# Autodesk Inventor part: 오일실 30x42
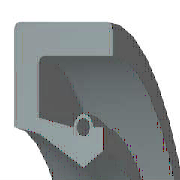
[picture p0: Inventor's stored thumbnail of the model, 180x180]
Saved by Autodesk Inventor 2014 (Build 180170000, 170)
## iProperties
IsCustomPart: 0
Company: 한국ATC센터
Created: 2009-02
Part Number: 오일실 30x42
Material: 고무
Description: 오일-실
Document SubType Name: Modeling
Standard: KS B 2804
Designer: KYOUNG IL JANG
Standards Organization: KS
Language: ko-KR
Size Designation: S - 30 42 8
Categories: <MemberInstance><Categories><Category DisplayName="샤프트 부품" InternalName="7f7aeb1f-a693-4053-b835-cee3144e0d98" Mnemonic="SHFT"><Category DisplayName="실링" Intern
Density: 0.93 g/cm^3
Appearance: 고무 - 검은색 - 버전 1.1
Author: KYOUNG IL JANG
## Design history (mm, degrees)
revolve "본체" stored, may be unused: angle "d17" = 90 deg
revolve "스프링1" stored, may be unused: angle "d18" = 90 deg
body "Solid1"
sketch "스케치1"
  geometry: L1 (0, 21)-(8, 21); L2 (8, 21)-(8, 19.75); L3 (8, 19.75)-(1.75, 19.75); L4 (0, 21)-(0, 17.1); L5 (0, 17.1)-(1.75, 16.75); L6 (1.75, 16.75)-(4.9, 15); L7 (4.9, 15)-(0, 15); L8 (6.3, 15.875)-(6.3, 17.1); L9 (0, 0)-(9.586, 0) reference; L10 (4.9, 15)-(6.3, 15.875); L11 (0, 18)-(0, -3) reference; L12 (-1.917, 0)-(11.503, 0) reference; L13 (4.2, 17.1)-(1.75, 17.59); L14 (1.75, 17.59)-(1.75, 19.75); L15 (6.3, 17.1)-(5.6, 17.1); C1 r 0.455 at (4.9, 17.1); A1 r 0.7 centre (4.9, 17.1) between (5.6, 17.1) and (4.2, 17.1)
  constraints: 26 end point, 5 horizontal alignment, 4 perpendicular, 2 centre point, 2 collinear, 2 horizontal, 2 parallel, 2 point on circle, 2 point on line, 2 vertical alignment, 1 coincident
  dimensions: "d0" = 42 diameter of L1 L9 (= SD2); "d1" = 31.75 diameter of L8.start L9 (= ABDM); "d2" = 1.25 distance of L1.end L2.end (computed from SD); "d3" = 0.91 diameter of C1 (= SPDI); "d4" = 1.4 diameter of A1 (= SPDA); "d5" = 30 diameter of L6.end L9 (= NND); "d6" = 33.5 diameter of L5.end L9 (= TKDM); "d7" = 34.2 diameter of L4.end L9 (= HLDM); "d8" = 4.9 distance from line of C1.centre L4 (= SPDST); "d9" = 6.3 distance between parallel lines of L8 L4 (= SDI); "d10" = 8 distance between parallel lines of L2 L4 (= SWDT); "d12" = 1.75 distance between parallel lines of L14 L4 (= SD)
fillet "모깎기1" dims "d11" = 0.4 (= RR)
other parameters: "SD2" = 42 [user parameter; used in 1 equation term], "SWDT" = 8 [user parameter; used in 1 equation term], "RR" = 0.4 [user parameter; used in 1 equation term], "SD" = 1.75 [user parameter; used in 2 equation terms], "NND" = 30 [user parameter; used in 1 equation term], "SPDA" = 1.4 [user parameter; used in 1 equation term], "SPDI" = 0.91 [user parameter; used in 1 equation term], "TKDM" = 33.5 [user parameter; used in 1 equation term], "HLDM" = 34.2 [user parameter; used in 1 equation term], "ABDM" = 31.75 [user parameter; used in 1 equation term], "SDI" = 6.3 [user parameter; used in 1 equation term], "SPDST" = 4.9 [user parameter; used in 1 equation term], "d13" = 0, "d14" = 0, "d15" = 0, "LAB" = 0.35 [user parameter]
